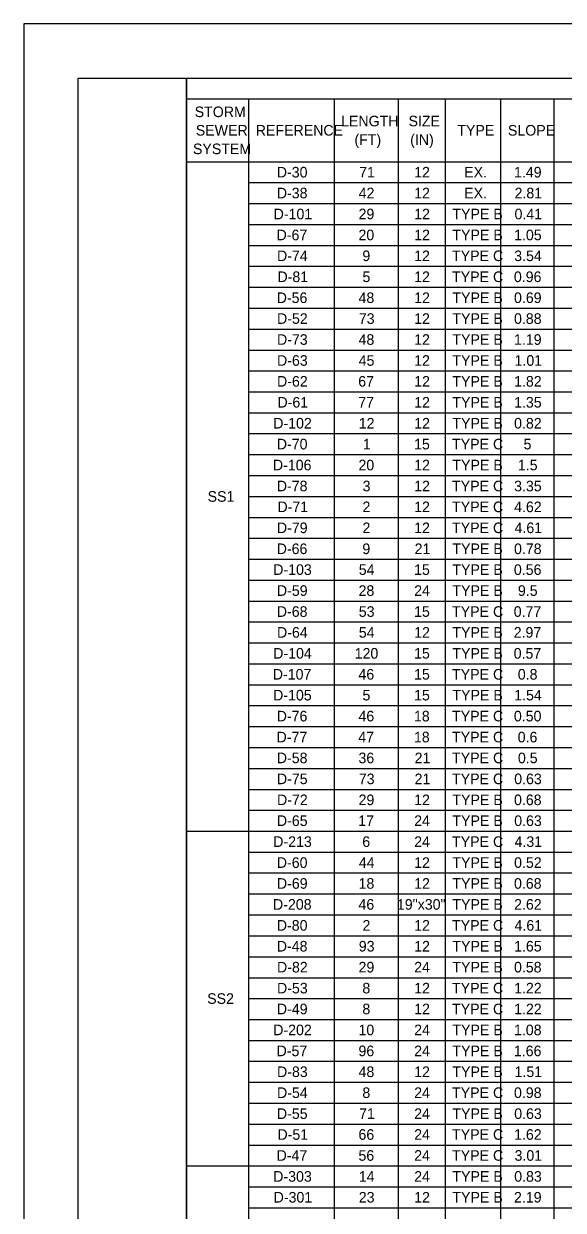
# Model space of a CAD drawing. Extents: x 0 to 34, y 0 to 22.
# Drawn here: x 0 to 4.97, y 11.07 to 22 of the extents above; entities that cross this region are included whole.
import ezdxf

# ---------------------------------------------------------------- set-up
doc = ezdxf.new("R2010")
doc.units = 0
for name, color, linetype in [('SH_Border', 7, 'Continuous'), ('SH_Cut_Line', 7, 'Continuous'), ('SH_Text', 7, 'Continuous')]:
    doc.layers.add(name, color=color, linetype=linetype)

msp = doc.modelspace()

# ---------------------------------------------------------------- linework, layer by layer
at = {"layer": 'SH_Border'}
for points in [[(0.5, 21.5), (1.5, 21.5), (1.5, 0.5), (0.5, 0.5)], [(1.5, 21.5), (33.5, 21.5), (33.5, 0.5), (1.5, 0.5)]]:
    msp.add_lwpolyline(points, close=True, dxfattribs=at)
at = {"layer": 'SH_Cut_Line'}
msp.add_lwpolyline([(0, 0), (34, 0), (34, 22), (0, 22)], close=True, dxfattribs=at)
at = {"layer": 'SH_Text'}
for p, q in [((1.5, 21.5), (11.162, 21.5)), ((1.5, 21.5), (1.5, 3.197)), ((1.5, 21.307), (11.162, 21.307)), ((2.068, 21.307), (2.068, 3.197)), ((2.858, 21.307), (2.858, 3.197)), ((3.446, 21.307), (3.446, 3.197)), ((3.879, 21.307), (3.879, 3.197)), ((4.39, 21.307), (4.39, 3.197)), ((4.881, 21.307), (4.881, 3.197)), ((1.5, 20.729), (11.162, 20.729)), ((2.068, 20.537), (11.162, 20.537)), ((2.068, 20.344), (11.162, 20.344)), ((2.068, 20.151), (11.162, 20.151)), ((2.068, 19.959), (11.162, 19.959)), ((2.068, 19.766), (11.162, 19.766)), ((2.068, 19.573), (11.162, 19.573)), ((2.068, 19.381), (11.162, 19.381)), ((2.068, 19.188), (11.162, 19.188)), ((2.068, 18.995), (11.162, 18.995)), ((2.068, 18.803), (11.162, 18.803)), ((2.068, 18.61), (11.162, 18.61)), ((2.068, 18.417), (11.162, 18.417)), ((2.068, 18.225), (11.162, 18.225)), ((2.068, 18.032), (11.162, 18.032)), ((2.068, 17.839), (11.162, 17.839)), ((2.068, 17.647), (11.162, 17.647)), ((2.068, 17.454), (11.162, 17.454)), ((2.068, 17.261), (11.162, 17.261)), ((2.068, 17.069), (11.162, 17.069)), ((2.068, 16.876), (11.162, 16.876)), ((2.068, 16.683), (11.162, 16.683)), ((2.068, 16.491), (11.162, 16.491)), ((2.068, 16.298), (11.162, 16.298)), ((2.068, 16.105), (11.162, 16.105)), ((2.068, 15.913), (11.162, 15.913)), ((2.068, 15.72), (11.162, 15.72)), ((2.068, 15.527), (11.162, 15.527)), ((2.068, 15.335), (11.162, 15.335)), ((2.068, 15.142), (11.162, 15.142)), ((2.068, 14.949), (11.162, 14.949)), ((2.068, 14.757), (11.162, 14.757)), ((1.5, 14.564), (11.162, 14.564)), ((2.068, 14.371), (11.162, 14.371)), ((2.068, 14.179), (11.162, 14.179)), ((2.068, 13.986), (11.162, 13.986)), ((2.068, 13.793), (11.162, 13.793)), ((2.068, 13.601), (11.162, 13.601)), ((2.068, 13.408), (11.162, 13.408)), ((2.068, 13.215), (11.162, 13.215)), ((2.068, 13.023), (11.162, 13.023)), ((2.068, 12.83), (11.162, 12.83)), ((2.068, 12.637), (11.162, 12.637)), ((2.068, 12.445), (11.162, 12.445)), ((2.068, 12.252), (11.162, 12.252)), ((2.068, 12.059), (11.162, 12.059)), ((2.068, 11.867), (11.162, 11.867)), ((2.068, 11.674), (11.162, 11.674)), ((1.5, 11.481), (11.162, 11.481)), ((2.068, 11.289), (11.162, 11.289)), ((2.068, 11.096), (11.162, 11.096))]:
    msp.add_line(p, q, dxfattribs=at)

# ---------------------------------------------------------------- texts
for s, p in [('STORM ', (1.574, 21.14)), ('LENGTH ', (2.922, 21.055)), ('SIZE ', (3.543, 21.055)), ('SEWER ', (1.584, 20.97)), ('REFERENCE', (2.136, 20.97)), ('(FT)', (3.045, 20.884)), ('(IN)', (3.558, 20.884)), ('TYPE', (3.992, 20.97)), ('SLOPE', (4.458, 20.97)), ('SYSTEM', (1.558, 20.799)), ('D-30', (2.33, 20.584)), ('71', (3.088, 20.584)), ('12', (3.595, 20.584)), ('EX.', (4.055, 20.584)), ('1.49', (4.514, 20.584)), ('D-38', (2.33, 20.392)), ('42', (3.084, 20.392)), ('12', (3.595, 20.392)), ('EX.', (4.055, 20.392)), ('2.81', (4.519, 20.392)), ('D-101', (2.301, 20.199)), ('29', (3.083, 20.199)), ('12', (3.595, 20.199)), ('TYPE B', (3.947, 20.199)), ('0.41', (4.519, 20.199)), ('D-67', (2.328, 20.006)), ('20', (3.082, 20.006)), ('12', (3.595, 20.006)), ('TYPE B', (3.947, 20.006)), ('1.05', (4.515, 20.006)), ('D-74', (2.332, 19.814)), ('9', (3.118, 19.814)), ('12', (3.595, 19.814)), ('TYPE C', (3.944, 19.814)), ('3.54', (4.516, 19.814)), ('D-81', (2.336, 19.621)), ('5', (3.119, 19.621)), ('12', (3.595, 19.621)), ('TYPE C', (3.944, 19.621)), ('0.96', (4.513, 19.621)), ('D-56', (2.329, 19.428)), ('48', (3.083, 19.428)), ('12', (3.595, 19.428)), ('TYPE B', (3.947, 19.428)), ('0.69', (4.514, 19.428)), ('D-52', (2.332, 19.236)), ('73', (3.085, 19.236)), ('12', (3.595, 19.236)), ('TYPE B', (3.947, 19.236)), ('0.88', (4.514, 19.236)), ('D-73', (2.332, 19.043)), ('48', (3.083, 19.043)), ('12', (3.595, 19.043)), ('TYPE B', (3.947, 19.043)), ('1.19', (4.514, 19.043)), ('D-63', (2.332, 18.85)), ('45', (3.084, 18.85)), ('12', (3.595, 18.85)), ('TYPE B', (3.947, 18.85)), ('1.01', (4.519, 18.85)), ('D-62', (2.332, 18.658)), ('67', (3.08, 18.658)), ('12', (3.595, 18.658)), ('TYPE B', (3.947, 18.658)), ('1.82', (4.515, 18.658)), ('D-61', (2.336, 18.465)), ('77', (3.08, 18.465)), ('12', (3.595, 18.465)), ('TYPE B', (3.947, 18.465)), ('1.35', (4.515, 18.465)), ('D-102', (2.297, 18.272)), ('12', (3.084, 18.272)), ('12', (3.595, 18.272)), ('TYPE B', (3.947, 18.272)), ('0.82', (4.515, 18.272)), ('D-70', (2.33, 18.08)), ('1', (3.123, 18.08)), ('15', (3.594, 18.08)), ('TYPE C', (3.944, 18.08)), ('5', (4.602, 18.08)), ('D-106', (2.294, 17.887)), ('20', (3.082, 17.887)), ('12', (3.595, 17.887)), ('TYPE B', (3.947, 17.887)), ('1.5', (4.55, 17.887)), ('D-78', (2.33, 17.694)), ('3', (3.12, 17.694)), ('12', (3.595, 17.694)), ('TYPE C', (3.944, 17.694)), ('3.35', (4.515, 17.694)), ('SS1', (1.693, 17.598)), ('D-71', (2.336, 17.502)), ('2', (3.119, 17.502)), ('12', (3.595, 17.502)), ('TYPE C', (3.944, 17.502)), ('4.62', (4.515, 17.502)), ('D-79', (2.331, 17.309)), ('2', (3.119, 17.309)), ('12', (3.595, 17.309)), ('TYPE C', (3.944, 17.309)), ('4.61', (4.519, 17.309)), ('D-66', (2.329, 17.116)), ('9', (3.118, 17.116)), ('21', (3.599, 17.116)), ('TYPE B', (3.947, 17.116)), ('0.78', (4.514, 17.116)), ('D-103', (2.297, 16.924)), ('54', (3.085, 16.924)), ('15', (3.594, 16.924)), ('TYPE B', (3.947, 16.924)), ('0.56', (4.513, 16.924)), ('D-59', (2.331, 16.731)), ('28', (3.083, 16.731)), ('24', (3.595, 16.731)), ('TYPE B', (3.947, 16.731)), ('9.5', (4.55, 16.731)), ('D-68', (2.33, 16.538)), ('53', (3.085, 16.538)), ('15', (3.594, 16.538)), ('TYPE C', (3.944, 16.538)), ('0.77', (4.511, 16.538)), ('D-64', (2.332, 16.346)), ('54', (3.085, 16.346)), ('12', (3.595, 16.346)), ('TYPE B', (3.947, 16.346)), ('2.97', (4.511, 16.346)), ('D-104', (2.297, 16.153)), ('120', (3.047, 16.153)), ('15', (3.594, 16.153)), ('TYPE B', (3.947, 16.153)), ('0.57', (4.511, 16.153)), ('D-107', (2.293, 15.96)), ('46', (3.082, 15.96)), ('15', (3.594, 15.96)), ('TYPE C', (3.944, 15.96)), ('0.8', (4.549, 15.96)), ('D-105', (2.296, 15.768)), ('5', (3.119, 15.768)), ('15', (3.594, 15.768)), ('TYPE B', (3.947, 15.768)), ('1.54', (4.516, 15.768)), ('D-76', (2.329, 15.575)), ('46', (3.082, 15.575)), ('18', (3.593, 15.575)), ('TYPE C', (3.944, 15.575)), ('0.50', (4.513, 15.575)), ('D-77', (2.328, 15.382)), ('47', (3.08, 15.382)), ('18', (3.593, 15.382)), ('TYPE C', (3.944, 15.382)), ('0.6', (4.548, 15.382)), ('D-58', (2.33, 15.19)), ('36', (3.082, 15.19)), ('21', (3.599, 15.19)), ('TYPE C', (3.944, 15.19)), ('0.5', (4.55, 15.19)), ('D-75', (2.331, 14.997)), ('73', (3.085, 14.997)), ('21', (3.599, 14.997)), ('TYPE C', (3.944, 14.997)), ('0.63', (4.516, 14.997)), ('D-72', (2.332, 14.804)), ('29', (3.083, 14.804)), ('12', (3.595, 14.804)), ('TYPE B', (3.947, 14.804)), ('0.68', (4.514, 14.804)), ('D-65', (2.331, 14.612)), ('17', (3.08, 14.612)), ('24', (3.595, 14.612)), ('TYPE B', (3.947, 14.612)), ('0.63', (4.516, 14.612)), ('D-213', (2.297, 14.419)), ('6', (3.117, 14.419)), ('24', (3.595, 14.419)), ('TYPE C', (3.944, 14.419)), ('4.31', (4.519, 14.419)), ('D-60', (2.33, 14.226)), ('44', (3.085, 14.226)), ('12', (3.595, 14.226)), ('TYPE B', (3.947, 14.226)), ('0.52', (4.515, 14.226)), ('D-69', (2.331, 14.034)), ('18', (3.083, 14.034)), ('12', (3.595, 14.034)), ('TYPE B', (3.947, 14.034)), ('0.68', (4.514, 14.034)), ('D-208', (2.295, 13.841)), ('46', (3.082, 13.841)), ('19"x30"', (3.436, 13.841)), ('TYPE B', (3.947, 13.841)), ('2.62', (4.515, 13.841)), ('D-80', (2.33, 13.648)), ('2', (3.119, 13.648)), ('12', (3.595, 13.648)), ('TYPE C', (3.944, 13.648)), ('4.61', (4.519, 13.648)), ('D-48', (2.33, 13.456)), ('93', (3.085, 13.456)), ('12', (3.595, 13.456)), ('TYPE B', (3.947, 13.456)), ('1.65', (4.515, 13.456)), ('D-82', (2.332, 13.263)), ('29', (3.083, 13.263)), ('24', (3.595, 13.263)), ('TYPE B', (3.947, 13.263)), ('0.58', (4.514, 13.263)), ('D-53', (2.332, 13.07)), ('8', (3.118, 13.07)), ('12', (3.595, 13.07)), ('TYPE C', (3.944, 13.07)), ('1.22', (4.515, 13.07)), ('SS2', (1.689, 12.974)), ('D-49', (2.331, 12.878)), ('8', (3.118, 12.878)), ('12', (3.595, 12.878)), ('TYPE C', (3.944, 12.878)), ('1.22', (4.515, 12.878)), ('D-202', (2.297, 12.685)), ('10', (3.082, 12.685)), ('24', (3.595, 12.685)), ('TYPE B', (3.947, 12.685)), ('1.08', (4.514, 12.685)), ('D-57', (2.328, 12.492)), ('96', (3.082, 12.492)), ('24', (3.595, 12.492)), ('TYPE B', (3.947, 12.492)), ('1.66', (4.513, 12.492)), ('D-83', (2.332, 12.3)), ('48', (3.083, 12.3)), ('12', (3.595, 12.3)), ('TYPE B', (3.947, 12.3)), ('1.51', (4.519, 12.3)), ('D-54', (2.332, 12.107)), ('8', (3.118, 12.107)), ('24', (3.595, 12.107)), ('TYPE C', (3.944, 12.107)), ('0.98', (4.514, 12.107)), ('D-55', (2.331, 11.914)), ('71', (3.088, 11.914)), ('24', (3.595, 11.914)), ('TYPE B', (3.947, 11.914)), ('0.63', (4.516, 11.914)), ('D-51', (2.336, 11.722)), ('66', (3.082, 11.722)), ('24', (3.595, 11.722)), ('TYPE C', (3.944, 11.722)), ('1.62', (4.515, 11.722)), ('D-47', (2.328, 11.529)), ('56', (3.082, 11.529)), ('24', (3.595, 11.529)), ('TYPE C', (3.944, 11.529)), ('3.01', (4.519, 11.529)), ('D-303', (2.297, 11.336)), ('14', (3.085, 11.336)), ('24', (3.595, 11.336)), ('TYPE B', (3.947, 11.336)), ('0.83', (4.516, 11.336)), ('D-301', (2.301, 11.144)), ('23', (3.085, 11.144)), ('12', (3.595, 11.144)), ('TYPE B', (3.947, 11.144)), ('2.19', (4.514, 11.144))]:
    msp.add_text(s, height=0.0975, dxfattribs=at).set_placement(p)

doc.saveas('drawing.dxf')
